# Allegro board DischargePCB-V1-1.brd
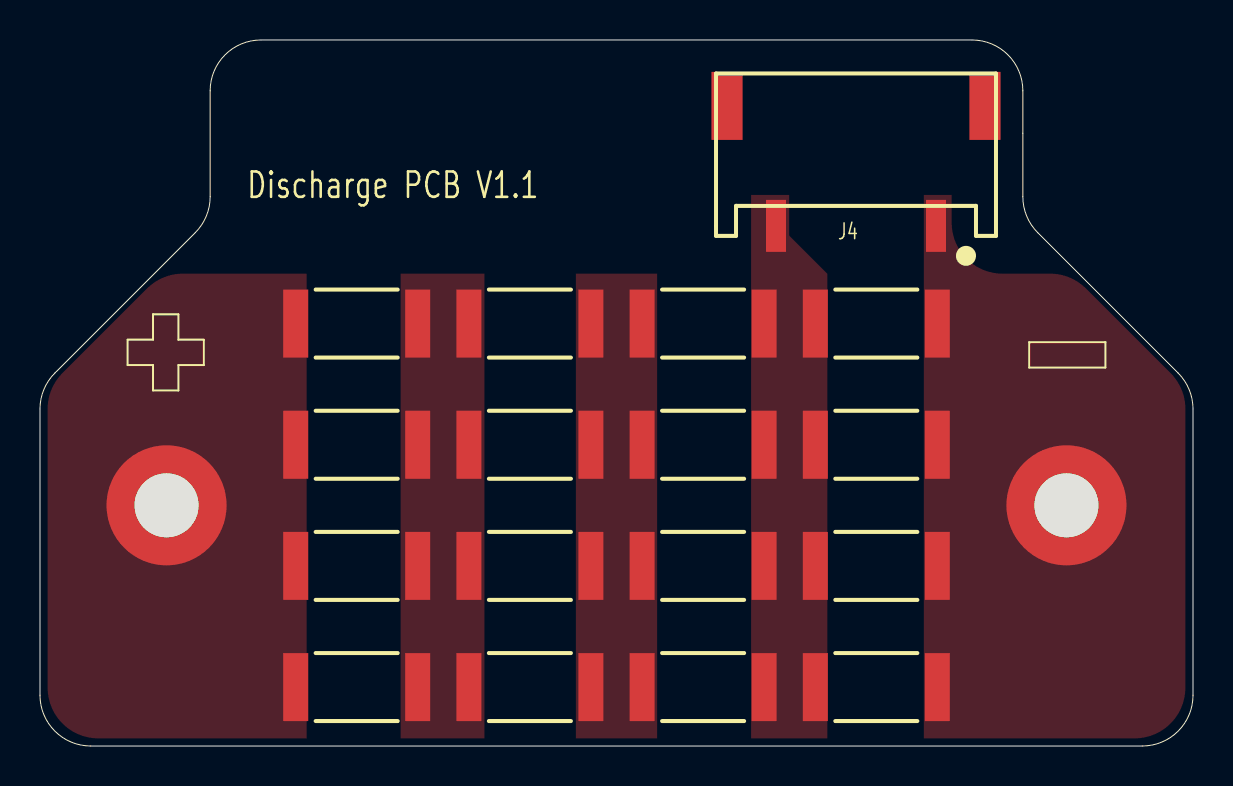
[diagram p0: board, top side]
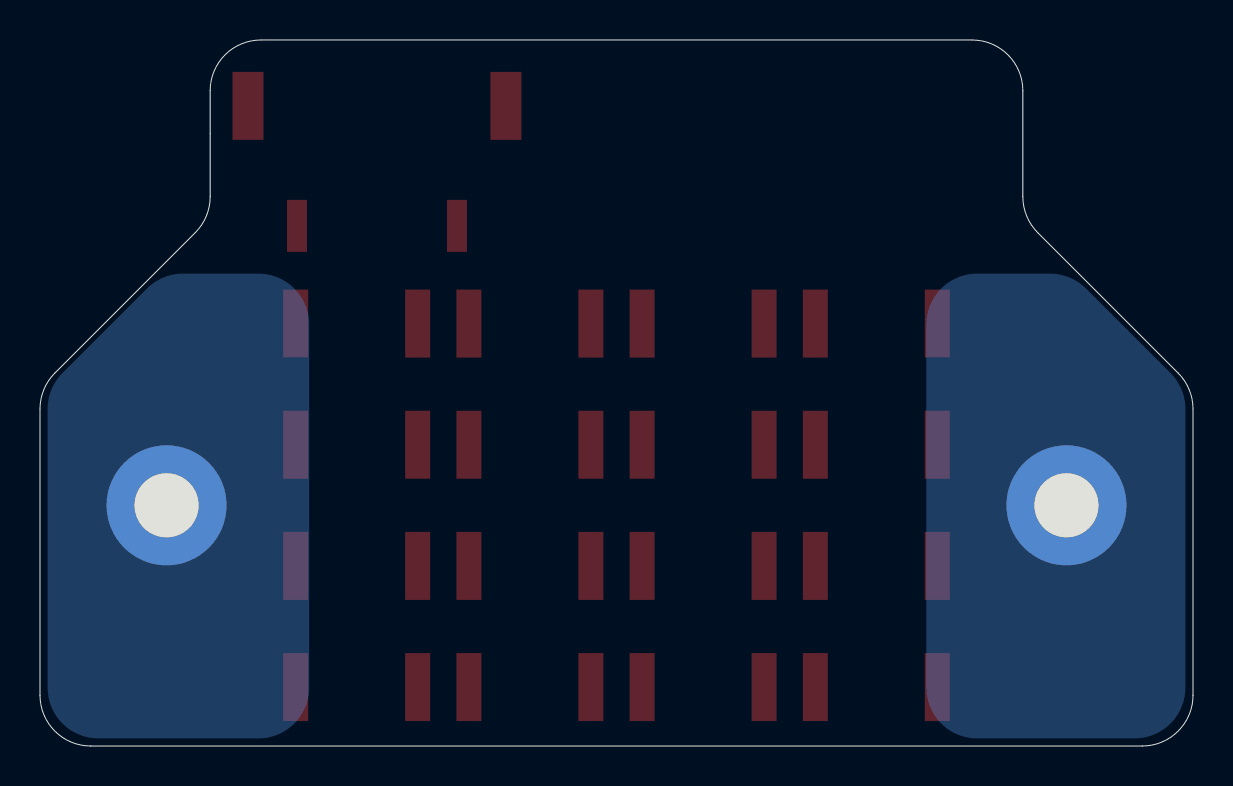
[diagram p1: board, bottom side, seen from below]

Outline 57.66 x 35.31 mm; copper layers: TOP, BOTTOM. Coordinates in mm from the lower left corner of the outline.
Outline path: 0,16.85 0,2.54 arc(0.74,0.74) 2.54,0 55.12,0 arc(56.91,0.74) 57.66,2.54 57.66,16.85 arc(57.46,17.83) 56.91,18.65 49.89,25.67 arc(49.34,26.5) 49.15,27.47 49.15,32.77 arc(48.41,34.56) 46.61,35.31 11.05,35.31 arc(9.25,34.56) 8.51,32.77 8.51,27.47 arc(8.32,26.5) 7.77,25.67 0.74,18.65 arc(0.19,17.83) 0,16.85

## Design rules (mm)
constraint set DEFAULT: min track width 0.178

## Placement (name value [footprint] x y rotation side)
J2  CON1  [CON_1X1]  6.33 12.04 0 top
J3  CON1  [CON_1X1]  51.33 12.04 0 top
J4  JST BH 8MM  [CON_JST-BHS-8MM-2PIN]  44.81 26.01 180 top
NOREF  -  []  25.44 0 90 top
R1  68kOhms  [RESC6432X70N]  15.84 2.95 0 top
R2  68kOhms  [RESC6432X70N]  24.5 2.95 0 top
R3  68kOhms  [RESC6432X70N]  33.16 2.95 0 top
R4  68kOhms  [RESC6432X70N]  41.82 2.95 0 top
R5  68kOhms  [RESC6432X70N]  15.84 9.01 0 top
R6  68kOhms  [RESC6432X70N]  24.5 9.01 0 top
R7  68kOhms  [RESC6432X70N]  33.16 9.01 0 top
R8  68kOhms  [RESC6432X70N]  41.82 9.01 0 top
R9  68kOhms  [RESC6432X70N]  15.84 15.07 0 top
R10  68kOhms  [RESC6432X70N]  24.5 15.07 0 top
R11  68kOhms  [RESC6432X70N]  33.16 15.07 0 top
R12  68kOhms  [RESC6432X70N]  41.82 15.07 0 top
R13  68kOhms  [RESC6432X70N]  15.84 21.12 0 top
R14  68kOhms  [RESC6432X70N]  24.5 21.12 0 top
R15  68kOhms  [RESC6432X70N]  33.16 21.12 0 top
R16  68kOhms  [RESC6432X70N]  41.82 21.12 0 top

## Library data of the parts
J2 J3 = CON1
J4 = CON2
R1-R16 = RES

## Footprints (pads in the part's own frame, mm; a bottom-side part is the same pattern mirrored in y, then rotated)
CON_1X1
  round 6 hole 3.2: 1(0,0)
CON_JST-BHS-8MM-2PIN
  rect 1.55x3.4 smd: (-2.45,-6) (10.45,-6)
  rect 1x2.6 smd: 1(0,0) 2(8,0)
RESC6432X70N
  rect 1.25x3.4 smd: 1(-3.05,0) 2(3.05,0)

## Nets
DC+: J2.1 R1.1 R5.1 R9.1 R13.1
DC-: J3.1 J4.1 R4.2 R8.2 R12.2 R16.2
N234316: R1.2 R2.1 R5.2 R6.1 R9.2 R10.1 R13.2 R14.1
N234320: R2.2 R3.1 R6.2 R7.1 R10.2 R11.1 R14.2 R15.1
N234326: J4.2 R3.2 R4.1 R7.2 R8.1 R11.2 R12.1 R15.2 R16.1

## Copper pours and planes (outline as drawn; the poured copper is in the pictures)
DC+ on BOTTOM: 10.8,23.62 12.59,22.88 13.34,21.08 13.34,2.92 12.59,1.12 10.8,0.38 2.92,0.38 1.12,1.12 0.38,2.92 0.38,16.85 0.57,17.83 1.12,18.65 5.35,22.88 6.18,23.43 7.15,23.62
DC- on TOP: 44.2,0.38 44.2,27.56 45.59,27.56 45.59,26.16 46.34,24.37 48.13,23.62 50.51,23.62 51.48,23.43 52.31,22.88 56.53,18.65 57.08,17.83 57.28,16.85 57.28,2.92 56.53,1.12 54.74,0.38
DC- on BOTTOM: 46.74,0.38 44.94,1.12 44.2,2.92 44.2,21.08 44.94,22.88 46.74,23.62 50.51,23.62 51.48,23.43 52.31,22.88 56.53,18.65 57.08,17.83 57.28,16.85 57.28,2.92 56.53,1.12 54.74,0.38
N234316 on TOP: 18.03,23.62 18.03,0.38 22.23,0.38 22.23,23.62
N234320 on TOP: 26.8,23.62 26.8,0.38 30.86,0.38 30.86,23.62
N234326 on TOP: 35.56,0.38 35.56,27.56 37.47,27.56 37.47,25.53 39.37,23.62 39.37,0.38

Small or netless copper shapes (teardrops, artwork), in the pictures only: 1 on TOP

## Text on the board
Ref Des/Silkscreen Top: Discharge PCB V1.1
XSECTION_CHART: *  SURFACE | L1 TOP CONDUCTOR | *  DIELECTRIC | L2 BOTTOM CONDUCTOR | DESIGN CROSS SECTION CHART | ___________________________ | TOTAL THICKNESS 62 MIL | 1-2 | FIGURE | FINISHED_SIZE | 125.98 | DRILL CHART: TOP to BOTTOM | ALL UNITS ARE IN MILS | PLATED | QTY | 2
